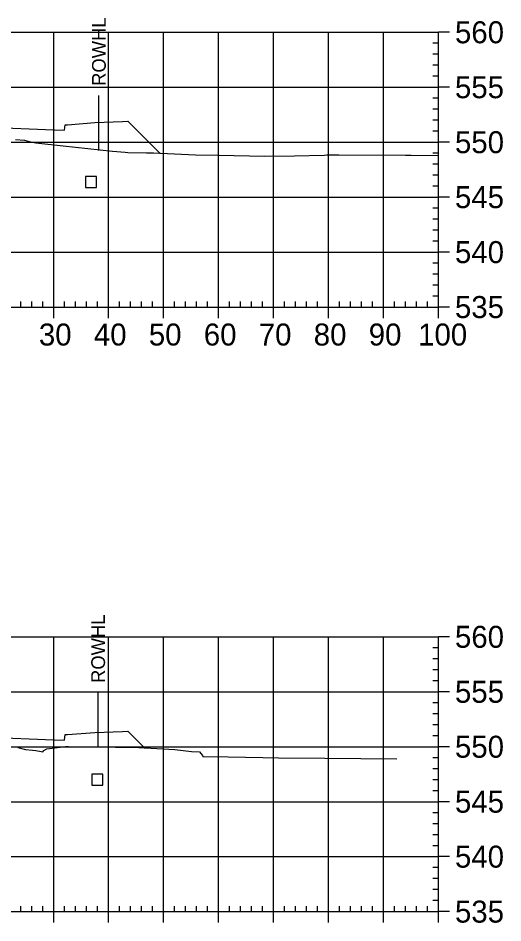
# Model space of a CAD drawing. Extents: x 708103 to 717568, y 374476 to 378707.
# Drawn here: x 711000.5 to 711088.7, y 376932.6 to 377097.2 of the extents above; entities that cross this region are included whole.
import ezdxf

# ---------------------------------------------------------------- set-up
doc = ezdxf.new("R2010")
doc.units = 0
for name, color, linetype in [('14', 7, 'Continuous'), ('22', 7, 'Continuous'), ('4', 7, 'Continuous'), ('57', 7, 'Continuous'), ('Existing', 7, 'Continuous'), ('XS_Right_of_Way', 7, 'Continuous')]:
    doc.layers.add(name, color=color, linetype=linetype)

msp = doc.modelspace()

# ---------------------------------------------------------------- linework, layer by layer
for points in [[(711006.93, 377075.15), (711007.03, 377075.15), (711007.03, 377075.25), (711006.93, 377075.25)], [(711006.93, 377072.15), (711007.03, 377072.15), (711007.03, 377072.25), (711006.93, 377072.25)], [(711006.93, 376964.2), (711007.03, 376964.2), (711007.03, 376964.3), (711006.93, 376964.3)], [(711006.93, 376961.2), (711007.03, 376961.2), (711007.03, 376961.3), (711006.93, 376961.3)]]:
    msp.add_lwpolyline(points, close=True)
at = {"layer": '14'}
for points in [[(711006.98, 377076.87), (711006.98, 377076.92), (711006.98, 377076.87), (711006.93, 377076.87), (711006.98, 377076.87), (711006.98, 377076.82), (711006.98, 377076.87), (711007.03, 377076.87)], [(711026.29, 377072.62), (711026.29, 377072.67), (711026.29, 377072.62), (711026.24, 377072.62), (711026.29, 377072.62), (711026.29, 377072.57), (711026.29, 377072.62), (711026.34, 377072.62)], [(711006.98, 376965.91), (711006.98, 376965.96), (711006.98, 376965.91), (711006.93, 376965.91), (711006.98, 376965.91), (711006.98, 376965.86), (711006.98, 376965.91), (711007.03, 376965.91)], [(711023.52, 376964.44), (711023.52, 376964.49), (711023.52, 376964.44), (711023.47, 376964.44), (711023.52, 376964.44), (711023.52, 376964.39), (711023.52, 376964.44), (711023.57, 376964.44)]]:
    msp.add_lwpolyline(points, dxfattribs=at)
at = {"layer": '22'}
for points in [[(710931.89, 377076.83), (710933.48, 377078.43), (710934.48, 377078.39), (710939.48, 377078.19), (710944.48, 377077.79), (710944.9, 377077.79), (710944.98, 377076.79), (710946.98, 377076.87), (710958.98, 377077.35), (710970.98, 377077.71), (710976.98, 377077.83), (710982.98, 377077.71), (710994.98, 377077.35), (711006.98, 377076.87), (711008.98, 377076.79), (711009.07, 377077.79), (711009.48, 377077.79), (711014.48, 377078.19), (711019.48, 377078.39), (711020.48, 377078.43), (711026.29, 377072.62)], [(710930.83, 376964.82), (710933.48, 376967.47), (710934.48, 376967.43), (710939.48, 376967.23), (710944.48, 376966.83), (710944.9, 376966.83), (710944.98, 376965.83), (710946.98, 376965.91), (710958.98, 376966.39), (710970.98, 376966.75), (710976.98, 376966.87), (710982.98, 376966.75), (710994.98, 376966.39), (711006.98, 376965.91), (711008.98, 376965.83), (711009.07, 376966.83), (711009.48, 376966.83), (711014.48, 376967.23), (711019.48, 376967.43), (711020.48, 376967.47), (711023.52, 376964.44)]]:
    msp.add_lwpolyline(points, dxfattribs=at)
at = {"layer": '4'}
for points in [[(711012.77, 377066.4), (711014.77, 377066.4), (711014.77, 377068.4), (711012.77, 377068.4)], [(711013.94, 376957.62), (711015.94, 376957.62), (711015.94, 376959.62), (711013.94, 376959.62)]]:
    msp.add_lwpolyline(points, close=True, dxfattribs=at)
at = {"layer": '57'}
for p, q in [((710876.98, 377094.63), (711076.98, 377094.63)), ((711006.98, 377044.63), (711006.98, 377094.63)), ((711016.98, 377044.63), (711016.98, 377094.63)), ((711026.98, 377044.63), (711026.98, 377094.63)), ((711036.98, 377044.63), (711036.98, 377094.63)), ((711046.98, 377044.63), (711046.98, 377094.63)), ((711056.98, 377044.63), (711056.98, 377094.63)), ((711066.98, 377044.63), (711066.98, 377094.63)), ((711076.98, 377044.63), (711076.98, 377094.63)), ((711076.98, 377044.63), (711076.98, 377094.63)), ((711078.98, 377094.63), (711076.98, 377094.63)), ((711076.98, 377092.63), (711075.98, 377092.63)), ((711076.98, 377090.63), (711075.98, 377090.63)), ((711076.98, 377088.63), (711075.98, 377088.63)), ((711076.98, 377086.63), (711075.98, 377086.63)), ((710876.98, 377084.63), (711076.98, 377084.63)), ((711078.98, 377084.63), (711076.98, 377084.63)), ((711076.98, 377082.63), (711075.98, 377082.63)), ((711076.98, 377080.63), (711075.98, 377080.63)), ((711076.98, 377078.63), (711075.98, 377078.63)), ((711076.98, 377076.63), (711075.98, 377076.63)), ((710876.98, 377074.63), (711076.98, 377074.63)), ((711078.98, 377074.63), (711076.98, 377074.63)), ((711076.98, 377072.63), (711075.98, 377072.63)), ((711076.98, 377070.63), (711075.98, 377070.63)), ((711076.98, 377068.63), (711075.98, 377068.63)), ((711076.98, 377066.63), (711075.98, 377066.63)), ((710876.98, 377064.63), (711076.98, 377064.63)), ((711078.98, 377064.63), (711076.98, 377064.63)), ((711076.98, 377062.63), (711075.98, 377062.63)), ((711076.98, 377060.63), (711075.98, 377060.63)), ((711076.98, 377058.63), (711075.98, 377058.63)), ((711076.98, 377056.63), (711075.98, 377056.63)), ((710876.98, 377054.63), (711076.98, 377054.63)), ((711078.98, 377054.63), (711076.98, 377054.63)), ((711076.98, 377052.63), (711075.98, 377052.63)), ((711076.98, 377050.63), (711075.98, 377050.63)), ((711076.98, 377048.63), (711075.98, 377048.63)), ((711076.98, 377046.63), (711075.98, 377046.63)), ((710876.98, 377044.63), (711076.98, 377044.63)), ((710876.98, 377044.63), (711076.98, 377044.63)), ((711000.98, 377044.63), (711000.98, 377045.63)), ((711002.98, 377044.63), (711002.98, 377045.63)), ((711004.98, 377044.63), (711004.98, 377045.63)), ((711006.98, 377042.63), (711006.98, 377044.63)), ((711008.98, 377044.63), (711008.98, 377045.63)), ((711010.98, 377044.63), (711010.98, 377045.63)), ((711012.98, 377044.63), (711012.98, 377045.63)), ((711014.98, 377044.63), (711014.98, 377045.63)), ((711016.98, 377042.63), (711016.98, 377044.63)), ((711018.98, 377044.63), (711018.98, 377045.63)), ((711020.98, 377044.63), (711020.98, 377045.63)), ((711022.98, 377044.63), (711022.98, 377045.63)), ((711024.98, 377044.63), (711024.98, 377045.63)), ((711026.98, 377042.63), (711026.98, 377044.63)), ((711028.98, 377044.63), (711028.98, 377045.63)), ((711030.98, 377044.63), (711030.98, 377045.63)), ((711032.98, 377044.63), (711032.98, 377045.63)), ((711034.98, 377044.63), (711034.98, 377045.63)), ((711036.98, 377042.63), (711036.98, 377044.63)), ((711038.98, 377044.63), (711038.98, 377045.63)), ((711040.98, 377044.63), (711040.98, 377045.63)), ((711042.98, 377044.63), (711042.98, 377045.63)), ((711044.98, 377044.63), (711044.98, 377045.63)), ((711046.98, 377042.63), (711046.98, 377044.63)), ((711048.98, 377044.63), (711048.98, 377045.63)), ((711050.98, 377044.63), (711050.98, 377045.63)), ((711052.98, 377044.63), (711052.98, 377045.63)), ((711054.98, 377044.63), (711054.98, 377045.63)), ((711056.98, 377042.63), (711056.98, 377044.63)), ((711058.98, 377044.63), (711058.98, 377045.63)), ((711060.98, 377044.63), (711060.98, 377045.63)), ((711062.98, 377044.63), (711062.98, 377045.63)), ((711064.98, 377044.63), (711064.98, 377045.63)), ((711066.98, 377042.63), (711066.98, 377044.63)), ((711068.98, 377044.63), (711068.98, 377045.63)), ((711070.98, 377044.63), (711070.98, 377045.63)), ((711072.98, 377044.63), (711072.98, 377045.63)), ((711074.98, 377044.63), (711074.98, 377045.63)), ((711076.98, 377042.63), (711076.98, 377044.63)), ((711078.98, 377044.63), (711076.98, 377044.63)), ((710876.98, 376984.63), (711076.98, 376984.63)), ((711006.98, 376934.63), (711006.98, 376984.63)), ((711016.98, 376934.63), (711016.98, 376984.63)), ((711026.98, 376934.63), (711026.98, 376984.63)), ((711036.98, 376934.63), (711036.98, 376984.63)), ((711046.98, 376934.63), (711046.98, 376984.63)), ((711056.98, 376934.63), (711056.98, 376984.63)), ((711066.98, 376934.63), (711066.98, 376984.63)), ((711076.98, 376934.63), (711076.98, 376984.63)), ((711076.98, 376934.63), (711076.98, 376984.63)), ((711078.98, 376984.63), (711076.98, 376984.63)), ((711076.98, 376982.63), (711075.98, 376982.63)), ((711076.98, 376980.63), (711075.98, 376980.63)), ((711076.98, 376978.63), (711075.98, 376978.63)), ((711076.98, 376976.63), (711075.98, 376976.63)), ((710876.98, 376974.63), (711076.98, 376974.63)), ((711078.98, 376974.63), (711076.98, 376974.63)), ((711076.98, 376972.63), (711075.98, 376972.63)), ((711076.98, 376970.63), (711075.98, 376970.63)), ((711076.98, 376968.63), (711075.98, 376968.63)), ((711076.98, 376966.63), (711075.98, 376966.63)), ((710876.98, 376964.63), (711076.98, 376964.63)), ((711078.98, 376964.63), (711076.98, 376964.63)), ((711076.98, 376962.63), (711075.98, 376962.63)), ((711076.98, 376960.63), (711075.98, 376960.63)), ((711076.98, 376958.63), (711075.98, 376958.63)), ((711076.98, 376956.63), (711075.98, 376956.63)), ((710876.98, 376954.63), (711076.98, 376954.63)), ((711078.98, 376954.63), (711076.98, 376954.63)), ((711076.98, 376952.63), (711075.98, 376952.63)), ((711076.98, 376950.63), (711075.98, 376950.63)), ((711076.98, 376948.63), (711075.98, 376948.63)), ((711076.98, 376946.63), (711075.98, 376946.63)), ((710876.98, 376944.63), (711076.98, 376944.63)), ((711078.98, 376944.63), (711076.98, 376944.63)), ((711076.98, 376942.63), (711075.98, 376942.63)), ((711076.98, 376940.63), (711075.98, 376940.63)), ((711076.98, 376938.63), (711075.98, 376938.63)), ((711000.98, 376934.63), (711000.98, 376935.63)), ((711002.98, 376934.63), (711002.98, 376935.63)), ((711004.98, 376934.63), (711004.98, 376935.63)), ((711008.98, 376934.63), (711008.98, 376935.63)), ((711010.98, 376934.63), (711010.98, 376935.63)), ((711012.98, 376934.63), (711012.98, 376935.63)), ((711014.98, 376934.63), (711014.98, 376935.63)), ((711018.98, 376934.63), (711018.98, 376935.63)), ((711020.98, 376934.63), (711020.98, 376935.63)), ((711022.98, 376934.63), (711022.98, 376935.63)), ((711024.98, 376934.63), (711024.98, 376935.63)), ((711028.98, 376934.63), (711028.98, 376935.63)), ((711030.98, 376934.63), (711030.98, 376935.63)), ((711032.98, 376934.63), (711032.98, 376935.63)), ((711034.98, 376934.63), (711034.98, 376935.63)), ((711038.98, 376934.63), (711038.98, 376935.63)), ((711040.98, 376934.63), (711040.98, 376935.63)), ((711042.98, 376934.63), (711042.98, 376935.63)), ((711044.98, 376934.63), (711044.98, 376935.63)), ((711048.98, 376934.63), (711048.98, 376935.63)), ((711050.98, 376934.63), (711050.98, 376935.63)), ((711052.98, 376934.63), (711052.98, 376935.63)), ((711054.98, 376934.63), (711054.98, 376935.63)), ((711058.98, 376934.63), (711058.98, 376935.63)), ((711060.98, 376934.63), (711060.98, 376935.63)), ((711062.98, 376934.63), (711062.98, 376935.63)), ((711064.98, 376934.63), (711064.98, 376935.63)), ((711068.98, 376934.63), (711068.98, 376935.63)), ((711070.98, 376934.63), (711070.98, 376935.63)), ((711072.98, 376934.63), (711072.98, 376935.63)), ((711074.98, 376934.63), (711074.98, 376935.63)), ((711076.98, 376936.63), (711075.98, 376936.63)), ((710876.98, 376934.63), (711076.98, 376934.63)), ((710876.98, 376934.63), (711076.98, 376934.63)), ((711006.98, 376932.63), (711006.98, 376934.63)), ((711016.98, 376932.63), (711016.98, 376934.63)), ((711026.98, 376932.63), (711026.98, 376934.63)), ((711036.98, 376932.63), (711036.98, 376934.63)), ((711046.98, 376932.63), (711046.98, 376934.63)), ((711056.98, 376932.63), (711056.98, 376934.63)), ((711066.98, 376932.63), (711066.98, 376934.63)), ((711076.98, 376932.63), (711076.98, 376934.63)), ((711078.98, 376934.63), (711076.98, 376934.63))]:
    msp.add_line(p, q, dxfattribs=at)
at = {"layer": 'Existing'}
for points in [[(711000.05, 377075.09), (711001.66, 377074.98), (711002.53, 377074.73), (711003.75, 377074.53), (711008.72, 377073.94), (711017.68, 377072.98), (711019.98, 377072.79), (711020.48, 377072.76), (711023.85, 377072.68), (711024.19, 377072.7), (711025.16, 377072.67), (711032.81, 377072.34), (711037.06, 377072.24), (711045.36, 377072.1), (711050.77, 377072.13), (711056.21, 377072.29), (711056.7, 377072.3), (711057.23, 377072.3), (711057.78, 377072.3), (711058.84, 377072.3), (711070.99, 377072.26), (711072.03, 377072.25), (711076.98, 377072.22)], [(711000.44, 376964.52), (711001.84, 376964.12), (711003.15, 376964.03), (711003.71, 376963.95), (711004.71, 376963.77), (711004.99, 376963.72), (711005.21, 376963.92), (711005.71, 376964.26), (711009.16, 376964.66), (711009.69, 376964.7), (711022.47, 376964.5), (711029.02, 376964.1), (711032.08, 376963.74), (711033.51, 376963.71), (711034.04, 376963.03), (711034.13, 376962.88), (711038.73, 376962.8), (711045.03, 376962.68), (711047.9, 376962.63), (711056.33, 376962.54), (711069.39, 376962.4)]]:
    msp.add_lwpolyline(points, dxfattribs=at)
at = {"layer": 'XS_Right_of_Way'}
for p, q in [((711015.14, 377083.12), (711015.14, 377073.12)), ((711015, 376974.48), (711015, 376964.48))]:
    msp.add_line(p, q, dxfattribs=at)

# ---------------------------------------------------------------- texts
at = {"layer": '14'}
for p in [(711014.45, 377077.47), (711019.45, 377078.34), (711019.45, 377077.67), (711019.45, 376967.38), (711019.45, 376966.72), (711014.45, 376966.52)]:
    msp.add_text('+', height=0.1, dxfattribs=at).set_placement(p)
at = {"layer": '57'}
for s, p in [('560', (711079.98, 377092.63)), ('555', (711079.98, 377082.63)), ('550', (711079.98, 377072.63)), ('545', (711079.98, 377062.63)), ('540', (711079.98, 377052.63)), ('535', (711079.98, 377042.63)), ('30', (711004.29, 377037.63)), ('40', (711014.29, 377037.63)), ('50', (711024.29, 377037.63)), ('60', (711034.29, 377037.63)), ('70', (711044.29, 377037.63)), ('80', (711054.29, 377037.63)), ('90', (711064.29, 377037.63)), ('100', (711073.28, 377037.63)), ('560', (711079.98, 376982.63)), ('555', (711079.98, 376972.63)), ('550', (711079.98, 376962.63)), ('545', (711079.98, 376952.63)), ('540', (711079.98, 376942.63)), ('535', (711079.98, 376932.63))]:
    msp.add_text(s, height=4, dxfattribs=at).set_placement(p)
at = {"layer": 'XS_Right_of_Way'}
for p in [(711016.46, 377084.88), (711016.32, 376976.24)]:
    msp.add_text('ROWHL', height=2.5, rotation=90, dxfattribs=at).set_placement(p)

doc.saveas('drawing.dxf')
